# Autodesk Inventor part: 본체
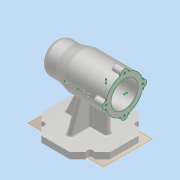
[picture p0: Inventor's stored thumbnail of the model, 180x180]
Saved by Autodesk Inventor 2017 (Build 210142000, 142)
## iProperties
Created: 2019-12
Part Number: 본체
Material: 알루미늄 6061
Document SubType Name: Modeling
Designer: 5-05-le
Density: 2.7 g/cm^3
Appearance: 알루미늄 - 평지
Mass: 725.934 g
Surface Area: 714.787 cm^2
Volume: 268.864 cm^3
Author: 5-05-le
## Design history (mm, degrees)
sketch "스케치1"
  geometry: 1 further point
sketch "스케치2"
  geometry: L1 (-45.045, -3.898)-(-45.045, 21.102); L2 (-45.045, 21.102)-(-20.045, 21.102); L3 (-20.045, 21.102)-(-0.045, 26.102); L4 (-0.045, 26.102)-(66.955, 26.102); L5 (66.955, 26.102)-(66.955, -3.898); L6 (66.955, -3.898)-(-45.045, -3.898); 1 further point
  constraints: 12 end point, 3 perpendicular, 1 horizontal, 1 vertical
  dimensions: "d0" = 112 distance between parallel lines of L5 L1; "d1" = 30 distance of L5.end L4.end; "d2" = 25 distance from line of L2.end L1; "d3" = 45 distance from line of L1 L3.end; "d4" = 25 distance of L1.start L1.end
revolve "회전1" sketch "스케치2" stored, may be unused: angle "d5" = 90 deg
sketch "스케치3"
  geometry: L1 (-45.045, -28.898)-(-45.045, 21.102) reference; L2 (-45.045, 21.102)-(-45.045, -3.898); L3 (-45.045, -3.898)-(66.955, -3.898); L4 (66.955, -33.898)-(66.955, 26.102) reference; L5 (66.955, -3.898)-(51.955, -3.898); L6 (51.955, -3.898)-(51.955, 17.102); L7 (51.955, 17.102)-(66.955, 17.102); L8 (66.955, 17.102)-(66.955, -3.898); L9 (51.955, -3.898)-(-2.045, -3.898); L10 (-2.045, -3.898)-(-2.045, 20.102); L11 (-2.045, 20.102)-(51.955, 20.102); L12 (51.955, 20.102)-(51.955, -3.898); L13 (-2.045, -3.898)-(-14.045, -3.898); L14 (-14.045, -3.898)-(-14.045, 17.102); L15 (-14.045, 17.102)-(-2.045, 17.102); L16 (-2.045, 17.102)-(-2.045, -3.898); L17 (-14.045, -3.898)-(-32.045, -3.898); L18 (-32.045, -3.898)-(-32.045, 13.602); L19 (-32.045, 13.602)-(-14.045, 13.602); L20 (-14.045, 13.602)-(-14.045, -3.898); L21 (-32.045, -3.898)-(-36.045, -3.898); L22 (-36.045, -3.898)-(-36.045, 12.102); L23 (-36.045, 12.102)-(-32.045, 12.102); L24 (-32.045, 12.102)-(-32.045, -3.898); L25 (-36.045, -3.898)-(-39.045, -3.898); L26 (-39.045, -3.898)-(-39.045, 6.602); L27 (-39.045, 6.602)-(-36.045, 6.602); L28 (-36.045, 6.602)-(-36.045, -3.898); 1 further point
  constraints: 52 end point, 12 parallel, 6 horizontal, 6 perpendicular, 2 midpoint
  dimensions: "d6" = 25 distance of L1.end L2.end (derived); "d7" = 15 distance of L6.end L7.end; "d8" = 21 distance of L5.end L6.end; "d9" = 54 distance of L10.end L11.end; "d10" = 24 distance of L9.end L10.end; "d11" = 12 distance of L14.end L15.end; "d12" = 21 distance of L13.end L14.end; "d13" = 18 distance of L18.end L19.end; "d14" = 17.5 distance of L17.end L18.end; "d15" = 4 distance of L22.end L23.end; "d16" = 16 distance of L21.end L22.end; "d17" = 3 distance of L26.end L27.end; "d18" = 10.5 distance of L25.end L26.end
revolve "회전2" sketch "스케치3" stored, may be unused: angle "d19" = 90 deg
fillet "모깎기1" dims "d20" = 3
fillet "모깎기2" dims "d21" = 0.3
chamfer "모따기1" distance "d22" = 1; stored, may be unused: second distance "d23" = 2, angle "d24" = 45 deg
sketch "스케치4"
  geometry: L1 (0, 0)-(-30, 0); C1 r 22 at (0, 0) reference; C2 r 6 at (-30, 0); 3 further points
  constraints: 2 coincident, 2 end point, 1 centre point, 1 horizontal, 1 horizontal alignment, 1 other
  dimensions: "d25" = 12 diameter of C2
extrude "돌출1" join sketch "스케치4" distance "d26" = 16; taper "d27" = 0 deg
sketch "스케치5"
  geometry: A1 r 6 centre (0, 0) between (0.6, 5.97) and (0.6, -5.97) reference; 2 further points
  constraints: 1 coincident
hole "구멍1" sketch "스케치5" at (0, 0) diameter "d28" = 3.242; stored, may be unused: countersink angle "d32" = 90 deg, drill point angle "d34" = 118 deg; dims "d29" = 8, "d30" = 4, "d31" = 2, "d33" = 11
fillet "모깎기3" dims "d35" = 3
fillet "모깎기4" dims "d36" = 1
fillet "모깎기5" dims "d40" = 3
fillet "모깎기6" dims "d41" = 1
fillet "모깎기7" dims "d42" = 3
fillet "모깎기8" dims "d43" = 10
node "작업 평면1"
sketch "스케치6"
  geometry: L1 (66.955, -2.277)-(66.955, -5.519) reference; L2 (66.955, -3.898)-(66.955, 32.102); L3 (66.955, 32.102)-(53.955, 32.102) reference; L4 (66.955, -3.898)-(10.955, -3.898); L5 (66.955, -27.094)-(34.151, -59.898); L6 (34.151, -59.898)-(-12.241, -59.898); L7 (-12.241, -59.898)-(-45.045, -27.094); L8 (-45.045, -27.094)-(-45.045, 19.298); L9 (-45.045, 19.298)-(-12.241, 52.102); L10 (-12.241, 52.102)-(34.151, 52.102); L11 (34.151, 52.102)-(66.955, 19.298); L12 (66.955, 19.298)-(66.955, -27.094); 2 further points
  constraints: 20 end point, 2 midpoint, 1 coincident, 1 horizontal, 1 point on line, 1 vertical, 17 other
  dimensions: "d45" = 56 distance of L2.start L4.end
extrude "돌출2" join sketch "스케치6" distance "d46" = 10; taper "d47" = 0 deg
sketch "스케치7"
  geometry: L1 (66.955, 19.298)-(34.151, 52.102) reference; L2 (-12.241, 52.102)-(-45.045, 19.298) reference; L3 (-45.045, -27.094)-(-12.241, -59.898) reference; L4 (34.151, -59.898)-(66.955, -27.094) reference; L5 (66.955, -27.094)-(66.955, 19.298) reference; L6 (66.955, -3.898)-(10.955, -3.898); L7 (10.955, -3.898)-(50.553, 35.7); L8 (66.955, 19.298)-(34.151, 52.102) reference; L9 (10.955, -3.898)-(-28.643, 35.7); L10 (10.955, -3.898)-(-28.643, -43.496); L11 (10.955, -3.898)-(50.553, -43.496); C1 r 5 at (50.553, 35.7); C2 r 5 at (-28.643, 35.7); C3 r 5 at (-28.643, -43.496); C4 r 5 at (50.553, -43.496); 1 further point
  constraints: 10 end point, 5 midpoint, 4 centre point, 4 coincident, 1 horizontal, 1 perpendicular
  dimensions: "d48" = 56 distance of L6.start L6.end; "d49" = 10 diameter of C1; "d50" = 10 diameter of C2; "d51" = 10 diameter of C3; "d52" = 10 diameter of C4
extrude "돌출3" cut sketch "스케치7" distance "d53" = 10; taper "d54" = 0 deg
sketch "스케치8"
  geometry: L1 (34.151, 52.102)-(-12.241, 52.102) reference; L2 (-45.045, 19.298)-(-45.045, -27.094) reference; L3 (-12.241, -59.898)-(34.151, -59.898) reference; L4 (66.955, -27.094)-(66.955, 19.298) reference; L5 (66.955, -3.898)-(41.955, -3.898); L6 (-45.045, -3.898)-(-27.045, -3.898); L7 (10.955, 52.102)-(10.955, 32.102); L8 (10.955, -59.898)-(10.955, -39.898); L9 (10.955, -39.898)-(6.955, -39.898); L10 (6.955, 32.102)-(14.955, 32.102); L11 (14.955, -39.898)-(10.955, -39.898); L12 (41.955, -3.898)-(41.955, 0.102); L13 (-27.045, -3.898)-(-27.045, 0.102); L14 (-27.045, -3.898)-(-27.045, -7.898); L15 (41.955, -7.898)-(41.955, -3.898); L16 (14.955, 32.102)-(14.955, 0.102); L17 (14.955, -7.898)-(14.955, -39.898); L18 (41.955, 0.102)-(14.955, 0.102); L19 (6.955, 0.102)-(-30.045, 0.102); L20 (-27.045, -7.898)-(6.955, -7.898); L21 (14.955, -7.898)-(41.955, -7.898); L22 (6.955, -39.898)-(6.955, -7.898); L23 (6.955, 0.102)-(6.955, 32.102); L24 (6.955, -7.898)-(14.955, -7.898); L25 (6.955, 0.102)-(14.955, 0.102); 1 further point
  constraints: 42 end point, 14 perpendicular, 4 horizontal, 4 midpoint, 3 vertical, 2 point on line, 1 parallel
  dimensions: "d55" = 25 distance of L5.start L5.end; "d56" = 18 distance of L6.start L6.end; "d57" = 20 distance of L7.start L7.end; "d58" = 20 distance of L8.start L8.end; "d59" = 4 distance of L8.end L9.end; "d60" = 8 distance of L10.start L10.end; "d61" = 4 distance of L5.end L12.end; "d62" = 4 distance of L6.end L14.end
extrude "돌출4" join sketch "스케치8" stored distance "d63" = 10; taper "d64" = 0 deg
feature "면 기울기1" dims angle "d65" = 25 deg
sketch "스케치9"
  geometry: 1 further point
node "작업 평면3"
  node "작업 평면2"
sketch "스케치10"
  geometry: 1 further point
sketch "스케치11"
  geometry: L1 (-59.898, -80)-(-59.898, -70) reference; L2 (-47.031, -70)-(-59.898, -70) reference; L3 (-39.96, -80)-(-39.96, -70) reference; L4 (-7.898, -70)-(0.102, -70) reference; A1 r 29.91 centre (-3.898, 0) between (0.102, -29.642) and (-7.898, -29.642) reference; 1 further point
feature "리브1" sketch "스케치11" dims "d70" = 1, "d71" = 8, "d72" = 0, "d73" = 0, "d74" = 1, "d75" = 1
sketch "스케치12"
  geometry: L1 (52.102, -80)-(52.102, -70) reference; L2 (52.102, -70)-(32.102, -70); L3 (30.7, -70)-(39.236, -70) reference; L4 (32.165, -70)-(14.737, -22.117); L5 (0, -70)-(32.165, -70); 1 further point
  constraints: 6 end point, 1 horizontal, 1 point on line
  dimensions: "d76" = 20 distance of L1.end L2.end; "d77" = 110 deg angle of L4 L2
feature "리브2" sketch "스케치12" dims "d78" = 1, "d79" = 8, "d80" = 0, "d81" = 0, "d82" = 1, "d83" = 1
fillet "모깎기9" dims "d84" = 3
fillet "모깎기10" dims "d85" = 3
sketch "스케치13"
  geometry: 1 further point
sketch "스케치14"
  geometry: C1 r 1.621 at (30, 30) reference; C2 r 1.621 at (60, 0) reference; C3 r 1.621 at (30, -30) reference; C4 r 22 at (30, 0) reference; C5 r 1.621 at (0, 0) reference; A1 r 30 centre (30, 0) between (23.229, 29.226) and (0.774, 6.771) reference; A2 r 1 centre (-0.2, 6.997) between (-0.171, 5.998) and (0.774, 6.771) reference; A3 r 6 centre (0, 0) between (-0.171, 5.998) and (-0.171, -5.998) reference; A4 r 1 centre (-0.2, -6.997) between (0.774, -6.771) and (-0.171, -5.998) reference; A5 r 30 centre (30, 0) between (0.774, -6.771) and (23.229, -29.226) reference; A6 r 1 centre (23.003, -30.2) between (24.002, -30.171) and (23.229, -29.226) reference; A7 r 6 centre (30, -30) between (24.002, -30.171) and (35.998, -30.171) reference; A8 r 1 centre (36.997, -30.2) between (36.771, -29.226) and (35.998, -30.171) reference; A9 r 30 centre (30, 0) between (36.771, -29.226) and (59.226, -6.771) reference; A10 r 1 centre (60.2, -6.997) between (60.171, -5.998) and (59.226, -6.771) reference; A11 r 6 centre (60, 0) between (60.171, -5.998) and (60.171, 5.998) reference; A12 r 1 centre (60.2, 6.997) between (59.226, 6.771) and (60.171, 5.998) reference; A13 r 30 centre (30, 0) between (59.226, 6.771) and (36.771, 29.226) reference; A14 r 1 centre (36.997, 30.2) between (35.998, 30.171) and (36.771, 29.226) reference; A15 r 6 centre (30, 30) between (35.998, 30.171) and (24.002, 30.171) reference; A16 r 1 centre (23.003, 30.2) between (23.229, 29.226) and (24.002, 30.171) reference; 1 further point
node "작업 평면4"
node "작업 평면5"
node "작업 평면6"
fillet "모깎기11" dims "d87" = 3
fillet "모깎기12" dims "d88" = 3
node "작업 평면7"
sketch "스케치15"
  geometry: L1 (0, 30.171)-(0, 36) reference; L2 (0, 0)-(46.847, 0); 2 further points
  constraints: 2 end point, 1 horizontal, 1 other
  dimensions: "d94" = 46 distance from line of L1 point (46, 0.171); "d95" = 30 vertical distance of L1.start point (46, 0.171)
sketch "3D 스케치1"
  node "투영 원본 위치 스케치15"
node "작업 평면8"
node "작업 평면9"
feature "엠보싱2" dims "d96" = 0.5, "d97" = 0
node "솔리드1"
pattern_circular "원형 패턴1" dims angle "d38" = 360 deg
mirror "미러1"
other parameters: "d66" = 67, "d67" = -56, "d86" = -3.898, "sa_0" = 4
